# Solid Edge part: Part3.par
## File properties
Author: Vicky Raina
Template: Normal.par
Last saved by: Robert a Rhodes jr
Revision: 3
Application: Solid Edge
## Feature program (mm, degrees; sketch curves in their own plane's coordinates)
body "unnamed Body 1"
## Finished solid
Body 1: solid body, 59 faces, 124 edges, 64 vertices.
  Faces by surface: plane 29, cylinder 25, cone 5
  Edges by curve: circle 60, line 54, intersection 10
Bounding box of the edges (mm): 1353.852 x 457.200 x 1295.400, from (-676.9261, -203.2, -533.4) to (676.9261, 254, 762).
Cylindrical faces by radius (mm): R50.8 x3, R95.25 x3, R127 x4, R152.4 x5, R254 x1, R431.8 x5, R508 x1, R533.4 x3
Conical faces (half-angle, radius in mm at the cone's reference point): 47.7263 deg R292.1 x5
Planar faces by outward normal: +x 1, +y 11, +z 1, -x 1, -y 2, -z 1, oblique 12
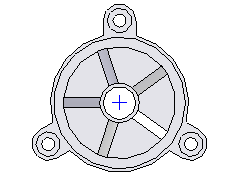
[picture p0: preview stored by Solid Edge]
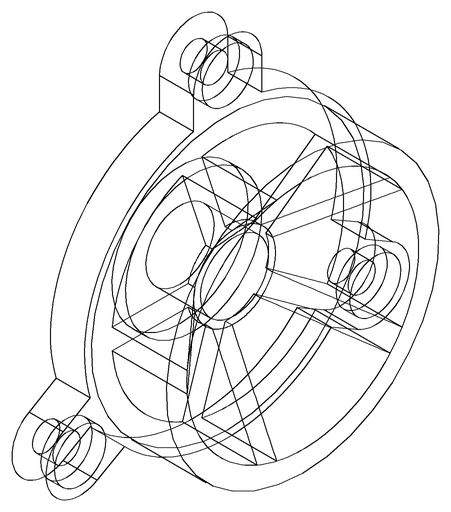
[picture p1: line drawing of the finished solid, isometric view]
